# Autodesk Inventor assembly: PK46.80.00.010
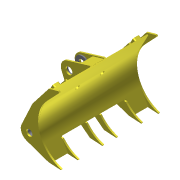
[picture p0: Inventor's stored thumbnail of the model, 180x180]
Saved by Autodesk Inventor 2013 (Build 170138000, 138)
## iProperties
Shininess: 64.0
Length Units: 11269
Angle Units: 11279
Time Units: 11290
Mass Units: 11283
Length Display Precision: 3
Angle Display Precision: 2
Compacted: True
Created: 2005-01
Part Number: PK46.80.00.010
Document SubType Name: Assembly
Designer: SAlex
Manufacturer: Standard
Standards Organization: Custom
Density: 0.0
Volumn: 0.0
Area: 0.0
PropertySet Name: Model Information
Control State: 0
Master: False
Checked Out: False
Checked Out Date: 2008-10-15
Last Check In Date: 2008-10-15
Author: SAlex
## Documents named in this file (9)
- D:\FrontLoaderVault\Data\Assy, Chassis, Front\PK46.80.00.010.iam
- D:\FrontLoaderVault\Data\Assy, Chassis, Front\PK46.80.00.012.ipt
- D:\FrontLoaderVault\Data\Assy, Chassis, Front\PK46.80.00.022.ipt
- D:\FrontLoaderVault\Data\Assy, Chassis, Front\PK46.80.00.015.ipt
- D:\FrontLoaderVault\Data\Assy, Chassis, Front\PK46.80.00.028.ipt
- D:\FrontLoaderVault\Data\Assy, Chassis, Front\PK46.25.02.003.ipt
- D:\FrontLoaderVault\Data\Assy, Chassis, Front\PK46.80.00.035.ipt
- D:\FrontLoaderVault\Data\Assy, Chassis, Front\PK46.80.00.034.ipt
- D:\FrontLoaderVault\Data\Assy, Chassis, Front\PK46.80.00.032.ipt
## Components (16 placed, 8 different names)
1. PK46.80.00.032:1 — Mate:3, Mate:5, Angle:1, Mate:24, Mate:25, Mate:26, Flush:24, Mate:33, Mate:38, Mate:39, Mate:40, Mate:41, Mate:42
2. PK46.80.00.012:1 — Flush:21, Mate:21, Insert:11, Mate:22, Flush:22, Mate:10, Mate:36, Mate:37, Mate:38
3. PK46.80.00.012:2 — Flush:21, Insert:10, Mate:23, Mate:37, Flush:27
4. PK46.25.02.003:1 — Insert:10
5. PK46.25.02.003:2 — Insert:11
6. PK46.80.00.034:2 — Insert:7, Flush:3, Mate:28, Mate:29, Mate:31, Mate:41, Flush:28
7. PK46.80.00.035:2 — Insert:6, Flush:3, Mate:21, Mate:29, Mate:31
8. PK46.80.00.035:1 — Insert:4, Flush:2, Mate:30, Mate:32
9. PK46.80.00.034:1 — Insert:5, Flush:2, Mate:3, Mate:27, Mate:30, Mate:32, Mate:40, Mate:42, Flush:28
10. PK46.80.00.015:1 — Insert:7, Mate:4, Flush:26
11. PK46.80.00.015:2 — Insert:6
12. PK46.80.00.015:3 — Insert:4
13. PK46.80.00.015:4 — Insert:5, Mate:4, Mate:7, Flush:25
14. PK46.80.00.022:1 — Mate:22, Mate:23, Flush:22, Mate:24, Flush:27
15. PK46.80.00.028:1 — Mate:25, Mate:27, Flush:23, Flush:24
16. PK46.80.00.028:2 — Mate:26, Flush:23, Mate:28
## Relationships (42: Mate 25, Flush 10, Insert 6, Angle 1)
- Insert:4: PK46.80.00.035:1 ↔ PK46.80.00.015:3
- Insert:5: PK46.80.00.034:1 ↔ PK46.80.00.015:4
- Insert:6: PK46.80.00.035:2 ↔ PK46.80.00.015:2
- Insert:7: PK46.80.00.034:2 ↔ PK46.80.00.015:1
- Flush:2: PK46.80.00.035:1 ↔ PK46.80.00.034:1
- Flush:3: PK46.80.00.034:2 ↔ PK46.80.00.035:2
- Mate:3: PK46.80.00.032:1 ↔ PK46.80.00.034:1
- Mate:4: PK46.80.00.015:1 ↔ PK46.80.00.015:4
- Mate:5: PK46.80.00.032:1
- Mate:7: PK46.80.00.015:4
- Angle:1: PK46.80.00.032:1
- Flush:21: PK46.80.00.012:1 ↔ PK46.80.00.012:2
- Mate:21: PK46.80.00.012:1 ↔ PK46.80.00.035:2
- Insert:10: PK46.80.00.012:2 ↔ PK46.25.02.003:1
- Insert:11: PK46.80.00.012:1 ↔ PK46.25.02.003:2
- Mate:22: PK46.80.00.012:1 ↔ PK46.80.00.022:1
- Mate:23: PK46.80.00.012:2 ↔ PK46.80.00.022:1
- Flush:22: PK46.80.00.012:1 ↔ PK46.80.00.022:1
- Mate:24: PK46.80.00.032:1 ↔ PK46.80.00.022:1
- Mate:25: PK46.80.00.032:1 ↔ PK46.80.00.028:1
- Mate:26: PK46.80.00.032:1 ↔ PK46.80.00.028:2
- Mate:27: PK46.80.00.034:1 ↔ PK46.80.00.028:1
- Flush:23: PK46.80.00.028:1 ↔ PK46.80.00.028:2
- Mate:28: PK46.80.00.034:2 ↔ PK46.80.00.028:2
- Flush:24: PK46.80.00.032:1 ↔ PK46.80.00.028:1
- Mate:29: PK46.80.00.034:2 ↔ PK46.80.00.035:2
- Mate:30: PK46.80.00.035:1 ↔ PK46.80.00.034:1
- Mate:31: PK46.80.00.034:2 ↔ PK46.80.00.035:2
- Mate:32: PK46.80.00.035:1 ↔ PK46.80.00.034:1
- Flush:25: PK46.80.00.015:4
- Flush:26: PK46.80.00.015:1
- Mate:33: PK46.80.00.032:1
- Mate:10: PK46.80.00.012:1
- Mate:36: PK46.80.00.012:1
- Mate:37: PK46.80.00.012:1 ↔ PK46.80.00.012:2
- Mate:38: PK46.80.00.032:1 ↔ PK46.80.00.012:1
- Flush:27: PK46.80.00.012:2 ↔ PK46.80.00.022:1
- Mate:39: PK46.80.00.032:1
- Mate:40: PK46.80.00.032:1 ↔ PK46.80.00.034:1
- Mate:41: PK46.80.00.032:1 ↔ PK46.80.00.034:2
- Mate:42: PK46.80.00.032:1 ↔ PK46.80.00.034:1
- Flush:28: PK46.80.00.034:2 ↔ PK46.80.00.034:1
